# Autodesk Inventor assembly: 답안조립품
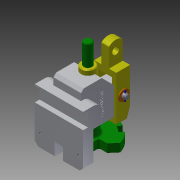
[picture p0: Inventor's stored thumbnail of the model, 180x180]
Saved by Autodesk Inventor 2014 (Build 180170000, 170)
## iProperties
Created: 2016-11
Part Number: 답안조립품
Document SubType Name: Assembly
Designer: owner
Author: owner
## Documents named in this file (8)
- C:\Users\owner\Desktop\461107V1015\답안조립품.iam
- C:\Users\owner\Desktop\461107V1015\본체.ipt
- C:\Users\owner\Desktop\461107V1015\부시.ipt
- C:\Users\owner\Desktop\461107V1015\분할대.ipt
- C:\Users\owner\Desktop\461107V1015\분할축.ipt
- C:\Users\owner\Desktop\461107V1015\와셔.ipt
- C:\Users\owner\Desktop\461107V1015\원통형핀.ipt
- C:\Users\owner\Desktop\461107V1015\클레비스핀.ipt
